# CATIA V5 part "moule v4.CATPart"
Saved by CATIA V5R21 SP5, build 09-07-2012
Part number: moule v4
Bounding box of the stored display mesh (mm): x -38.5 to 38.5, y -28.5 to 28.5, z -6 to 6
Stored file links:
  \\salsa.univ-amu.fr\dfs\myhome_etud\DOSSIERS_WINDOWS\Documents\stage s4\CAO\v4\moule v4.CATPart
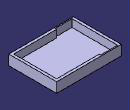
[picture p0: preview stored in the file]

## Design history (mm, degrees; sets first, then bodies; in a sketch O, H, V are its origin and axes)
Body1 (main body)
  Sketch1 on xy-plane, origin (0, 0, 0), H (1, 0, 0), V (0, 1, 0)
    line L1 (-38.5, 28.5) -> (38.5, 28.5)
    line L2 (38.5, 28.5) -> (38.5, -28.5)
    line L3 (38.5, -28.5) -> (-38.5, -28.5)
    line L4 (-38.5, -28.5) -> (-38.5, 28.5)
    distance L4 L2 = 77
    length L2 = 57
    horizontal: L1 H, L3 H
    vertical: L2 V, L4 V
    symmetry: L2 L4 V, L3 L1 H
  Pad1: profile Sketch1, direction (0, 0, 1), length 6, mirrored extent
  Sketch2 on end face of Pad1, origin (0, 0, 6), H (1, 0, 0), V (0, 1, 0)
    line L1 (35.5, -25.5) -> (-35.5, -25.5)
    line L2 (-35.5, -25.5) -> (-35.5, 25.5)
    line L3 (-35.5, 25.5) -> (35.5, 25.5)
    line L4 (35.5, 25.5) -> (35.5, -25.5)
    reference projected line E1 (38.5, -28.5) -> (38.5, 28.5) from edge [face of Pad1 from Sketch1.L2 | end face of Pad1]
    reference projected line E2 (38.5, 28.5) -> (-38.5, 28.5) from edge [face of Pad1 from Sketch1.L1 | end face of Pad1]
    distance L4 E1 = 3
    distance L3 E2 = 3
    horizontal: L1 H, L3 H
    vertical: L2 V, L4 V
    symmetry: L4 L2 V, L1 L3 H
  Pocket1: profile Sketch2, direction (0, 0, -1), length 9
  Sketch3 on end face of Pad1, origin (0, 0, 6), H (1, 0, 0), V (0, 1, 0)
    line L1 (-35.5, 27.25) -> (-15.5, 27.25)
    line L2 (-15.5, 27.25) -> (-15.5, -27.25)
    line L3 (-15.5, -27.25) -> (-35.5, -27.25)
    line L4 (-35.5, -27.25) -> (-35.5, 27.25)
    reference projected line E1 (-38.5, 28.5) -> (-38.5, -28.5) from edge [face of Pad1 from Sketch1.L4 | end face of Pad1]
    distance L4 E1 = 3
    distance L3 L1 = 54.5
    length L1 = 20
    horizontal: L1 H, L3 H
    vertical: L2 V, L4 V
    symmetry: L1 L3 H
  Pocket2: profile Sketch3, direction (0, 0, -1), length 9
